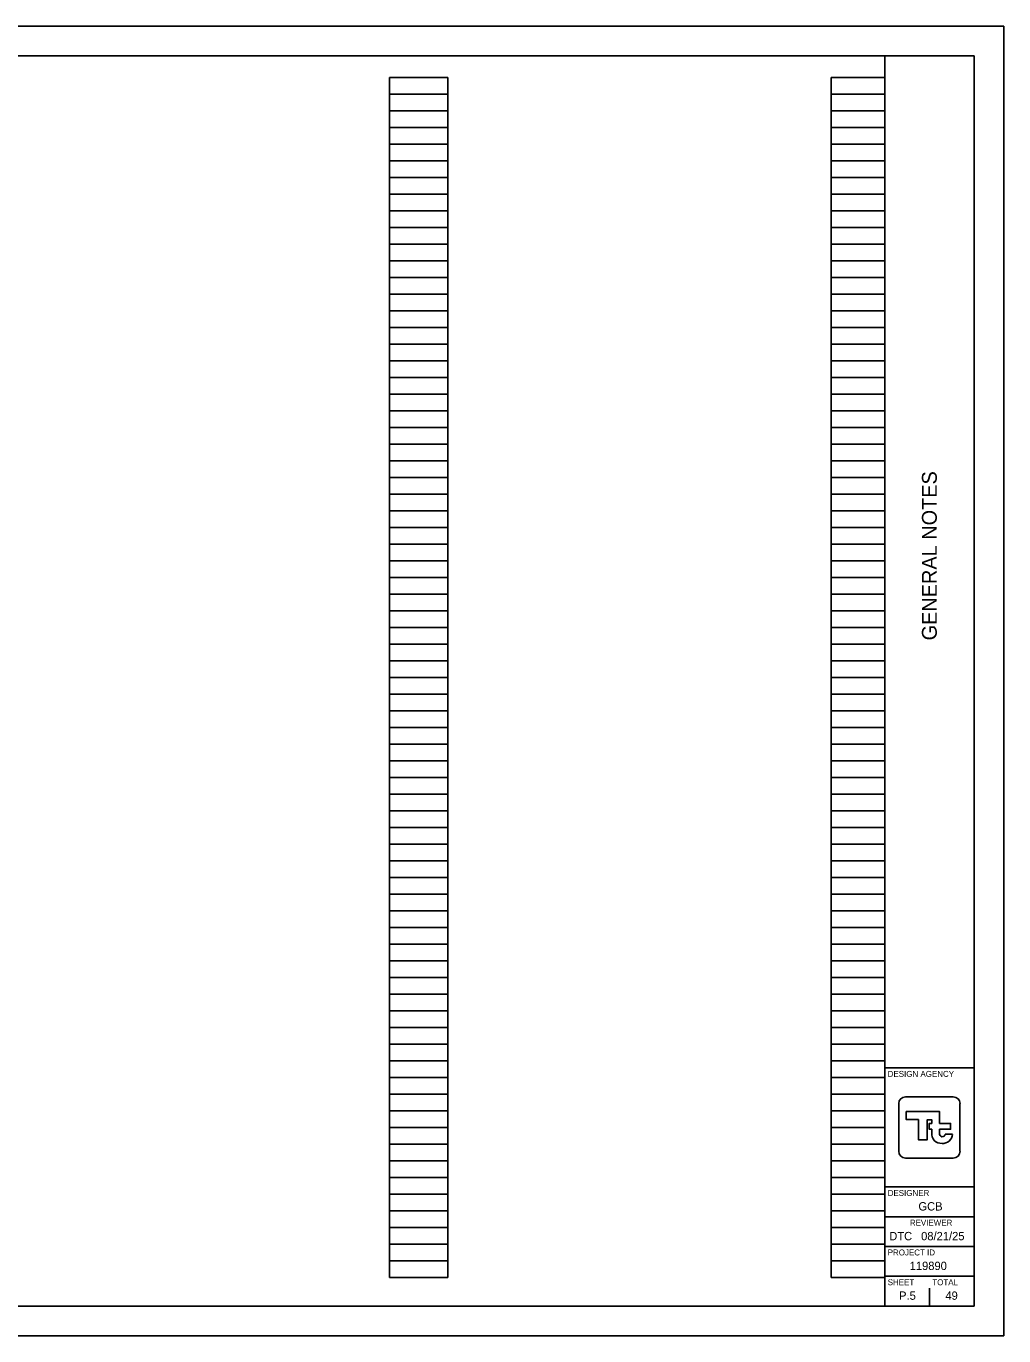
# Model space of a CAD drawing. Extents: x 0 to 34, y 0 to 22.
# Drawn here: x 17.58 to 34, y 0 to 22 of the extents above; entities that cross this region are included whole.
import ezdxf

# ---------------------------------------------------------------- set-up
doc = ezdxf.new("R2010")
doc.units = 0
for name, color, linetype in [('SH_Border', 7, 'Continuous'), ('SH_Cut_Line', 7, 'Continuous'), ('SH_Data', 7, 'Continuous')]:
    doc.layers.add(name, color=color, linetype=linetype)

msp = doc.modelspace()

# ---------------------------------------------------------------- linework, layer by layer
at = {"layer": 'SH_Border'}
for p, q in [((32, 0.5), (32, 21.5)), ((32, 4.5), (33.5, 4.5)), ((32, 2.5), (33.5, 2.5)), ((32, 2), (33.5, 2)), ((32, 1.5), (33.5, 1.5)), ((32, 1), (33.5, 1))]:
    msp.add_line(p, q, dxfattribs=at)
msp.add_lwpolyline([(1.5, 21.5), (33.5, 21.5), (33.5, 0.5), (1.5, 0.5)], close=True, dxfattribs=at)
at = {"layer": 'SH_Cut_Line'}
msp.add_lwpolyline([(0, 0), (34, 0), (34, 22), (0, 22)], close=True, dxfattribs=at)
at = {"layer": 'SH_Data'}
for p, q in [((23.68, 0.98), (23.68, 21.14)), ((23.68, 21.14), (24.66, 21.14)), ((24.66, 0.98), (24.66, 21.14)), ((31.1, 0.98), (31.1, 21.14)), ((31.1, 21.14), (32, 21.14)), ((32, 0.98), (32, 21.14)), ((23.68, 20.86), (24.66, 20.86)), ((31.1, 20.86), (32, 20.86)), ((23.68, 20.58), (24.66, 20.58)), ((31.1, 20.58), (32, 20.58)), ((23.68, 20.3), (24.66, 20.3)), ((31.1, 20.3), (32, 20.3)), ((23.68, 20.02), (24.66, 20.02)), ((31.1, 20.02), (32, 20.02)), ((23.68, 19.74), (24.66, 19.74)), ((31.1, 19.74), (32, 19.74)), ((23.68, 19.46), (24.66, 19.46)), ((31.1, 19.46), (32, 19.46)), ((23.68, 19.18), (24.66, 19.18)), ((31.1, 19.18), (32, 19.18)), ((23.68, 18.9), (24.66, 18.9)), ((31.1, 18.9), (32, 18.9)), ((23.68, 18.62), (24.66, 18.62)), ((31.1, 18.62), (32, 18.62)), ((23.68, 18.34), (24.66, 18.34)), ((31.1, 18.34), (32, 18.34)), ((23.68, 18.06), (24.66, 18.06)), ((31.1, 18.06), (32, 18.06)), ((23.68, 17.78), (24.66, 17.78)), ((31.1, 17.78), (32, 17.78)), ((23.68, 17.5), (24.66, 17.5)), ((31.1, 17.5), (32, 17.5)), ((23.68, 17.22), (24.66, 17.22)), ((31.1, 17.22), (32, 17.22)), ((23.68, 16.94), (24.66, 16.94)), ((31.1, 16.94), (32, 16.94)), ((23.68, 16.66), (24.66, 16.66)), ((31.1, 16.66), (32, 16.66)), ((23.68, 16.38), (24.66, 16.38)), ((31.1, 16.38), (32, 16.38)), ((23.68, 16.1), (24.66, 16.1)), ((31.1, 16.1), (32, 16.1)), ((23.68, 15.82), (24.66, 15.82)), ((31.1, 15.82), (32, 15.82)), ((23.68, 15.54), (24.66, 15.54)), ((31.1, 15.54), (32, 15.54)), ((23.68, 15.26), (24.66, 15.26)), ((31.1, 15.26), (32, 15.26)), ((23.68, 14.98), (24.66, 14.98)), ((31.1, 14.98), (32, 14.98)), ((23.68, 14.7), (24.66, 14.7)), ((31.1, 14.7), (32, 14.7)), ((23.68, 14.42), (24.66, 14.42)), ((31.1, 14.42), (32, 14.42)), ((23.68, 14.14), (24.66, 14.14)), ((31.1, 14.14), (32, 14.14)), ((23.68, 13.86), (24.66, 13.86)), ((31.1, 13.86), (32, 13.86)), ((23.68, 13.58), (24.66, 13.58)), ((31.1, 13.58), (32, 13.58)), ((23.68, 13.3), (24.66, 13.3)), ((31.1, 13.3), (32, 13.3)), ((23.68, 13.02), (24.66, 13.02)), ((31.1, 13.02), (32, 13.02)), ((23.68, 12.74), (24.66, 12.74)), ((31.1, 12.74), (32, 12.74)), ((23.68, 12.46), (24.66, 12.46)), ((31.1, 12.46), (32, 12.46)), ((23.68, 12.18), (24.66, 12.18)), ((31.1, 12.18), (32, 12.18)), ((23.68, 11.9), (24.66, 11.9)), ((31.1, 11.9), (32, 11.9)), ((23.68, 11.62), (24.66, 11.62)), ((31.1, 11.62), (32, 11.62)), ((23.68, 11.34), (24.66, 11.34)), ((31.1, 11.34), (32, 11.34)), ((23.68, 11.06), (24.66, 11.06)), ((31.1, 11.06), (32, 11.06)), ((23.68, 10.78), (24.66, 10.78)), ((31.1, 10.78), (32, 10.78)), ((23.68, 10.5), (24.66, 10.5)), ((31.1, 10.5), (32, 10.5)), ((23.68, 10.22), (24.66, 10.22)), ((31.1, 10.22), (32, 10.22)), ((23.68, 9.94), (24.66, 9.94)), ((31.1, 9.94), (32, 9.94)), ((23.68, 9.66), (24.66, 9.66)), ((31.1, 9.66), (32, 9.66)), ((23.68, 9.38), (24.66, 9.38)), ((31.1, 9.38), (32, 9.38)), ((23.68, 9.1), (24.66, 9.1)), ((31.1, 9.1), (32, 9.1)), ((23.68, 8.82), (24.66, 8.82)), ((31.1, 8.82), (32, 8.82)), ((23.68, 8.54), (24.66, 8.54)), ((31.1, 8.54), (32, 8.54)), ((23.68, 8.26), (24.66, 8.26)), ((31.1, 8.26), (32, 8.26)), ((23.68, 7.98), (24.66, 7.98)), ((31.1, 7.98), (32, 7.98)), ((23.68, 7.7), (24.66, 7.7)), ((31.1, 7.7), (32, 7.7)), ((23.68, 7.42), (24.66, 7.42)), ((31.1, 7.42), (32, 7.42)), ((23.68, 7.14), (24.66, 7.14)), ((31.1, 7.14), (32, 7.14)), ((23.68, 6.86), (24.66, 6.86)), ((31.1, 6.86), (32, 6.86)), ((23.68, 6.58), (24.66, 6.58)), ((31.1, 6.58), (32, 6.58)), ((23.68, 6.3), (24.66, 6.3)), ((31.1, 6.3), (32, 6.3)), ((23.68, 6.02), (24.66, 6.02)), ((31.1, 6.02), (32, 6.02)), ((23.68, 5.74), (24.66, 5.74)), ((31.1, 5.74), (32, 5.74)), ((23.68, 5.46), (24.66, 5.46)), ((31.1, 5.46), (32, 5.46)), ((23.68, 5.18), (24.66, 5.18)), ((31.1, 5.18), (32, 5.18)), ((23.68, 4.9), (24.66, 4.9)), ((31.1, 4.9), (32, 4.9)), ((23.68, 4.62), (24.66, 4.62)), ((31.1, 4.62), (32, 4.62)), ((23.68, 4.34), (24.66, 4.34)), ((31.1, 4.34), (32, 4.34)), ((23.68, 4.06), (24.66, 4.06)), ((31.1, 4.06), (32, 4.06)), ((23.68, 3.78), (24.66, 3.78)), ((31.1, 3.78), (32, 3.78)), ((23.68, 3.5), (24.66, 3.5)), ((31.1, 3.5), (32, 3.5)), ((32.75, 3.5), (32.75, 3.5)), ((32.791, 3.415), (32.791, 3.415)), ((33.136, 3.385), (33.015, 3.385)), ((23.68, 3.22), (24.66, 3.22)), ((31.1, 3.22), (32, 3.22)), ((23.68, 2.94), (24.66, 2.94)), ((31.1, 2.94), (32, 2.94)), ((23.68, 2.66), (24.66, 2.66)), ((31.1, 2.66), (32, 2.66)), ((23.68, 2.38), (24.66, 2.38)), ((31.1, 2.38), (32, 2.38)), ((23.68, 2.1), (24.66, 2.1)), ((31.1, 2.1), (32, 2.1)), ((23.68, 1.82), (24.66, 1.82)), ((31.1, 1.82), (32, 1.82)), ((23.68, 1.54), (24.66, 1.54)), ((31.1, 1.54), (32, 1.54)), ((23.68, 1.26), (24.66, 1.26)), ((31.1, 1.26), (32, 1.26)), ((23.68, 0.98), (24.66, 0.98)), ((31.1, 0.98), (32, 0.98)), ((32.375, 0.675), (32.375, 0.675)), ((32.75, 0.5), (32.75, 0.8))]:
    msp.add_line(p, q, dxfattribs=at)
for points in [[(32.348, 4.014), (33.152, 4.014)], [(32.236, 3.099), (32.236, 3.901)], [(32.922, 3.399), (32.922, 3.47), (33.107, 3.47), (33.107, 3.568), (32.922, 3.568), (32.922, 3.768), (32.361, 3.768), (32.361, 3.632), (32.566, 3.632), (32.566, 3.294), (32.715, 3.294), (32.715, 3.63), (32.79, 3.63), (32.79, 3.568), (32.748, 3.568), (32.748, 3.47), (32.79, 3.47), (32.79, 3.415), (32.791, 3.415)], [(33.264, 3.901), (33.264, 3.099)], [(33.152, 2.986), (32.348, 2.986)]]:
    msp.add_lwpolyline(points, dxfattribs=at)
for centre, radius, start, end in [((32.348, 3.901), 0.113, 90, 180), ((33.152, 3.901), 0.113, 360, 90), ((32.949, 3.392), 0.16, 171.8856, 274.8323), ((32.968, 3.392), 0.0473, 171.8856, 350.9243), ((32.976, 3.392), 0.16, 265.1677, 357.3201), ((32.348, 3.099), 0.113, 180, 270), ((33.152, 3.099), 0.113, 270, 360)]:
    msp.add_arc(centre, radius, start, end, dxfattribs=at)

# ---------------------------------------------------------------- texts
msp.add_text('GENERAL NOTES', height=0.25, rotation=90, dxfattribs=at).set_placement((32.875, 11.682))
for s, height, p in [('DESIGN AGENCY', 0.1, (32.05, 4.35)), ('DESIGNER', 0.1, (32.05, 2.35)), ('GCB', 0.14, (32.566, 2.105)), ('REVIEWER', 0.1, (32.422, 1.85)), ('DTC', 0.14, (32.076, 1.605)), ('08/21/25', 0.14, (32.611, 1.605)), ('PROJECT ID', 0.1, (32.05, 1.35)), ('119890', 0.14, (32.419, 1.105)), ('SHEET', 0.1, (32.05, 0.85)), ('TOTAL', 0.1, (32.8, 0.85)), ('P.5', 0.14, (32.241, 0.605)), ('49', 0.14, (33.019, 0.605))]:
    msp.add_text(s, height=height, dxfattribs=at).set_placement(p)

doc.saveas('drawing.dxf')
